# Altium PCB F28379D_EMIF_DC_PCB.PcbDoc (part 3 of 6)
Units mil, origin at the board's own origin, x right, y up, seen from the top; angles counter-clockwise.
Board outline 3000 x 1480 mil, 6 copper layers (Top Layer, Signal Layer 1, Signal Layer 2, Signal Layer 3, Signal Layer 4, Bottom Layer), stack 61.4 mil thick; 51 components, 68 nets, 414 pads, 205 vias.
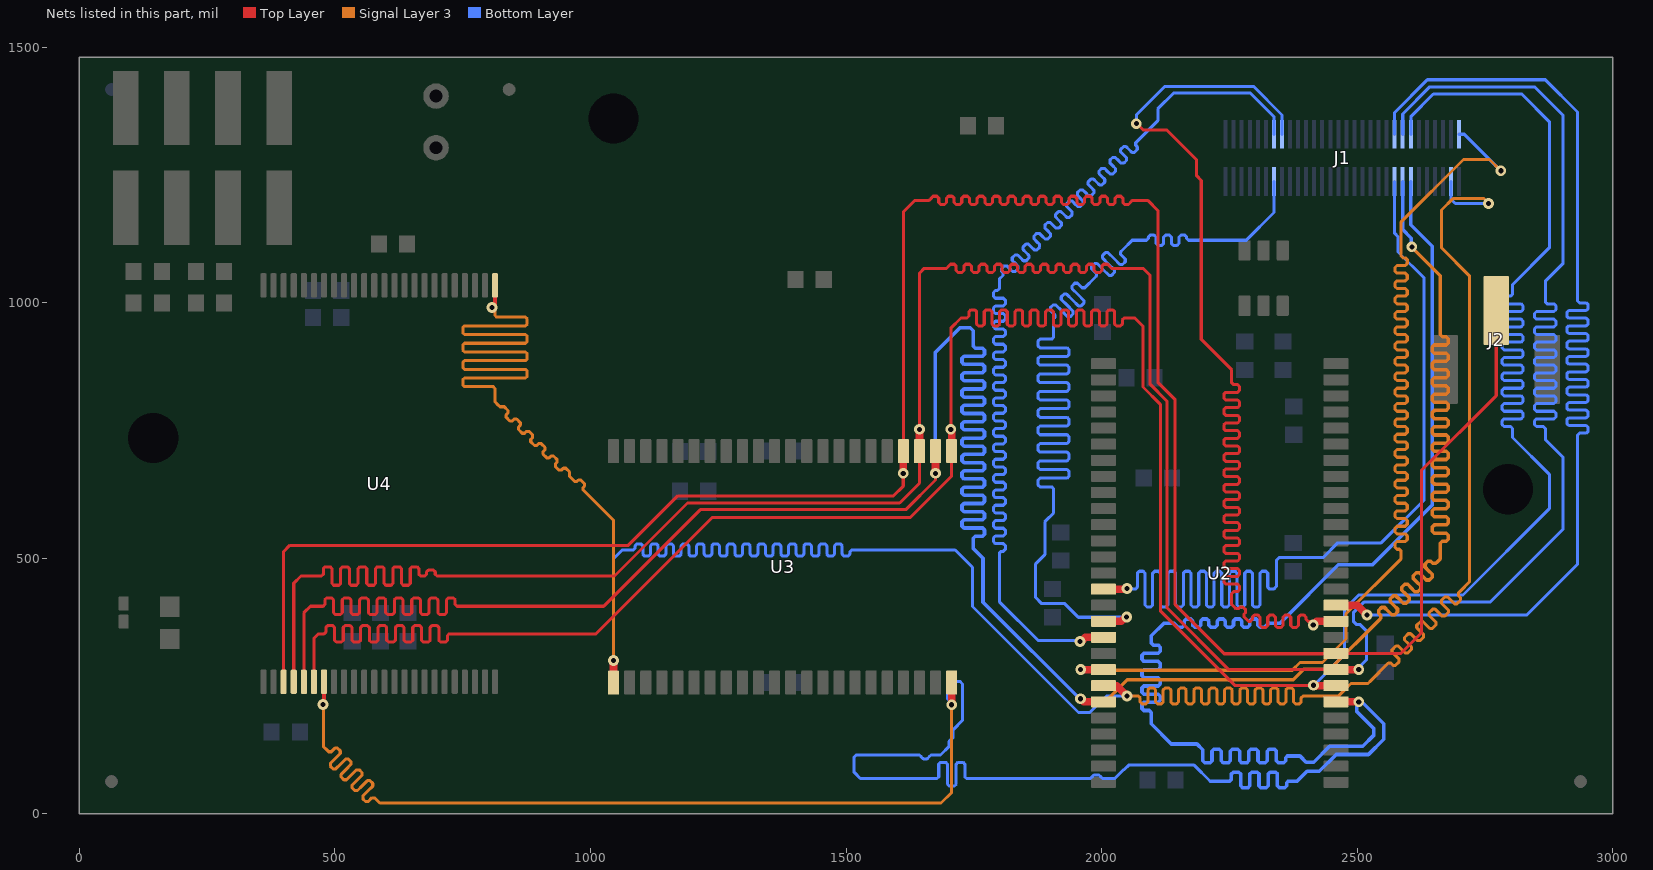
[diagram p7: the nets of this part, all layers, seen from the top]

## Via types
v1: diameter 21, hole 10, Top Layer to Bottom Layer, 204 vias
v2: diameter 20, hole 10, Top Layer to Bottom Layer, 1 vias

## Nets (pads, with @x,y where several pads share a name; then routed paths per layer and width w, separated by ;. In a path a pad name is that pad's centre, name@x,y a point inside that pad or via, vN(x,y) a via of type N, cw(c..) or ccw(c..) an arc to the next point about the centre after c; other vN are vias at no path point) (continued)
EM_A8: J1.13@2604.86,1236.74 U2.33 U3.22 U4.7 | length 6445.8
  Top Layer w8: U4.7@478.73,258.2 478.73,218.27 v1@479,218
  Top Layer w15: v1@1706.71,221.29 U3.22@1706.71,256.62 ; U2.33@2458.36,219.03 v1@2499.03,219.03
  Signal Layer 3 w6: v1@478,218 478,131 485,124 487.65,121.35 492.95,121.35 500.01,128.4 505.31,128.4 510.61,123.1 510.61,117.79 500.91,108.09 491.21,98.39 491.21,93.08 496.51,87.78 501.81,87.78 511.52,97.48 521.22,107.19 526.52,107.19 531.83,101.88 531.83,96.58 522.12,86.88 512.42,77.17 512.42,71.87 517.72,66.57 523.03,66.57 532.73,76.27 542.43,85.97 547.74,85.97 553.04,80.67 553.04,75.37 543.34,65.66 533.63,55.96 533.63,50.66 538.94,45.35 544.24,45.35 553.94,55.06 563.65,64.76 568.95,64.76 574.25,59.46 574.25,54.15 564.55,44.45 554.85,34.75 554.85,29.44 560.15,24.14 565.45,24.14 572.5,31.19 577.81,31.19 588,21 1686,21 1706.71,41.71 v1(1706.71,213.29) v1@1706.71,217.29
  Bottom Layer w6: v1@1706.71,217.29 1699,225 1699,245.62 1712.38,259 1723,259 1728,254 1728,182.75 1709.56,164.31 1709.56,149.25 1705.81,145.5 1705.75,145.5 1702,141.75 1702,132 1685,115 1677.5,115 1666.25,115 1662.5,111.25 1662.5,111.19 1658.75,107.44 1651.25,107.44 1647.5,111.19 1647.5,111.25 1643.75,115 1636,115 1520,115 1516,111 1516,81 1528,69 1673,69 1678.1,69 1681.5,72.4 1681.5,97.12 1684.9,100.52 1695.1,100.52 1698.5,97.12 1698.5,69 1698.5,57.88 1701.9,54.48 1712.1,54.48 1715.5,57.88 1715.5,69 1715.5,97.12 1718.9,100.52 1729.1,100.52 1732.5,97.12 1732.5,72.4 1735.9,69 1817,69 1973,69 1978.1,69 1981.5,72.4 1984.9,75.8 1995.1,75.8 1998.5,72.4 2001.9,69 2016,69 2026,69 2043.5,86.5 2044.5,86.5 2053,95 2181,95 2212,64 2213,64
  Bottom Layer w7: v1@1706.71,221.29 v1@1708.71,219.29 ; 2213,64 2250.4,64 2254,67.6 2254,77.89 2257.6,81.49 2268.4,81.49 2272,77.89 2272,64 2272,54.61 2275.6,51.01 2286.4,51.01 2290,54.61 2290,64 2290,77.89 2293.6,81.49 2304.4,81.49 2308,77.89 2308,64 2308,54.61 2311.6,51.01 2322.4,51.01 2326,54.61 2326,64 2326,77.89 2329.6,81.49 2340.4,81.49 2344,77.89 2344,64 2344,54.61 2347.6,51.01 2358.4,51.01 2362,54.61 2362,60.4 2365.6,64 2371,64 2383,64 2402,83 2426,83 2459,116 2522,116 2552,146 2552,176 2508.97,219.03 v1(2503.03,219.03) 2499.03,219.03 2499.03,199.97 2532,167 2532,153 2511,132 2446,132 2415,101 2400,101 2388,113 2369,113 2363.6,113 2360,109.4 2360,103.62 2356.4,100.02 2345.6,100.02 2342,103.62 2342,113 2342,122.38 2338.4,125.98 2327.6,125.98 2324,122.38 2324,113 2324,103.62 2320.4,100.02 2309.6,100.02 2306,103.62 2306,113 2306,122.38 2302.4,125.98 2291.6,125.98 2288,122.38 2288,113 2288,103.62 2284.4,100.02 2273.6,100.02 2270,103.62 2270,113 2270,122.38 2266.4,125.98 2255.6,125.98 2252,122.38 2252,113 2252,103.62 2248.4,100.02 2237.6,100.02 2234,103.62 2234,113 2234,122.38 2230.4,125.98 2219.6,125.98 2216,122.38 2216,113 2216,103.62 2212.4,100.02 2201.6,100.02 2198,103.62 2198,109.4 2198,125 2186.5,136.5 2136.5,136.5 2097,176 2097,188 2097,198 2093,202 2083,202 2079,206 2079,214 2083,218 2097,218 2111,218 2115,222 2115,230 2111,234 2097,234 2083,234 2079,238 2079,246 2083,250 2097,250 2111,250 2115,254 2115,262 2111,266 2097,266 2083,266 2079,270 2079,278 2083,282 2097,282 2111,282 2115,286 2115,294 2111,298 2097,298 2083,298 2079,302 2079,310 2083,314 2097,314 2111,314 2115,318 2115,326 2111,330 2101,330 2097,334 2097,338 2097,348 2122,373 2130,373 2142,373 2146,369 2150,365 2158,365 2162,369 2162,373 2162,377 2166,381 2174,381 2178,377 2178,373 2178,369 2182,365 2190,365 2194,369 2194,373 2194,377 2198,381 2206,381 2210,377 2210,373 2210,369 2214,365 2222,365 2226,369 2226,373 2226,377 2230,381 2238,381 2242,377 2242,373 2242,369 2246,365 2254,365 2258,369 2258,373 2258,377 2262,381 2270,381 2274,377 2274,373 2274,369 2278,365 2286,365 2290,369 2290,373 2290,377 2294,381 2302,381 2306,377 2306,373 2306,369 2310,365 2318,365 2322,369 2326,373 2338,373 2346,373 2349,373 2463,487 2530,487 2647,604 2647,1110 2604.86,1152.14 J1.13@2604.86,1236.74
  other v1: 477,214
EM_A9: J1.14@2604.86,1329.26 U2.34 U3.23 U4.6 | length 6494.5
  Top Layer w6: U4.6@459.05,258.2 459.05,343.05 468,352 474,352 479.1,352 482.5,355.4 482.5,364.6 485.9,368 496.1,368 499.5,364.6 499.5,352 499.5,339.4 502.9,336 513.1,336 516.5,339.4 516.5,352 516.5,364.6 519.9,368 530.1,368 533.5,364.6 533.5,352 533.5,339.4 536.9,336 547.1,336 550.5,339.4 550.5,352 550.5,364.6 553.9,368 564.1,368 567.5,364.6 567.5,352 567.5,339.4 570.9,336 581.1,336 584.5,339.4 584.5,352 584.5,364.6 587.9,368 598.1,368 601.5,364.6 601.5,352 601.5,339.4 604.9,336 615.1,336 618.5,339.4 618.5,352 618.5,364.6 621.9,368 632.1,368 635.5,364.6 635.5,352 635.5,339.4 638.9,336 649.1,336 652.5,339.4 652.5,352 652.5,364.6 655.9,368 666.1,368 669.5,364.6 669.5,352 669.5,339.4 672.9,336 683.1,336 686.5,339.4 686.5,352 686.5,364.6 689.9,368 700.1,368 703.5,364.6 703.5,352 703.5,339.4 706.9,336 717.1,336 720.5,339.4 720.5,348.6 723.9,352 882,352 1011,352 1239,580 1626,580 1706.71,660.71 U3.23@1706.71,709.38 ; v1(1705,752) 1705,950 1725,970 1733,970 1736.75,970 1740.5,973.75 1740.5,982.18 1744.25,985.93 1751.75,985.93 1755.5,982.18 1755.5,970 1755.5,957.82 1759.25,954.07 1766.75,954.07 1770.5,957.82 1770.5,970 1770.5,982.18 1774.25,985.93 1781.75,985.93 1785.5,982.18 1785.5,970 1785.5,957.82 1789.25,954.07 1796.75,954.07 1800.5,957.82 1800.5,970 1800.5,982.18 1804.25,985.93 1811.75,985.93 1815.5,982.18 1815.5,970 1815.5,957.82 1819.25,954.07 1826.75,954.07 1830.5,957.82 1830.5,970 1830.5,982.18 1834.25,985.93 1841.75,985.93 1845.5,982.18 1845.5,970 1845.5,957.82 1849.25,954.07 1856.75,954.07 1860.5,957.82 1860.5,970 1860.5,982.18 1864.25,985.93 1871.75,985.93 1875.5,982.18 1875.5,970 1875.5,957.82 1879.25,954.07 1886.75,954.07 1890.5,957.82 1890.5,970 1890.5,982.18 1894.25,985.93 1901.75,985.93 1905.5,982.18 1905.5,970 1905.5,957.82 1909.25,954.07 1916.75,954.07 1920.5,957.82 1920.5,970 1920.5,982.18 1924.25,985.93 1931.75,985.93 1935.5,982.18 1935.5,970 1935.5,957.82 1939.25,954.07 1946.75,954.07 1950.5,957.82 1950.5,970 1950.5,982.18 1954.25,985.93 1961.75,985.93 1965.5,982.18 1965.5,970 1965.5,957.82 1969.25,954.07 1976.75,954.07 1980.5,957.82 1980.5,970 1980.5,982.18 1984.25,985.93 1991.75,985.93 1995.5,982.18 1995.5,970 1995.5,957.82 1999.25,954.07 2006.75,954.07 2010.5,957.82 2010.5,970 2010.5,982.18 2014.25,985.93 2021.75,985.93 2025.5,982.18 2025.5,970 2025.5,957.82 2029.25,954.07 2036.75,954.07 2040.5,957.82 2040.5,966.25 2044.25,970 2060,970 2065,970 2081,954 2081,835 2115,801 2115,397 2261.47,250.53 v1@2414.47,250.53 ; v1@1707,749 v1@1708,750
  Top Layer w15: v1(1705,752) 1706.71,750.29 U3.23@1706.71,709.38 ; v1@2414.47,250.53 U2.34@2458.36,250.53
  Bottom Layer w6: v1@2411.47,250.53 2411.53,250.53 v1@2413,252 ; v1@2414.47,250.53 2475,311.06 2475,400 2503,428 2707,428 2876,597 2876,664 2804,736 2804,737 2804,753.75 2800.25,757.5 2787.26,757.5 2783.51,761.25 2783.51,768.75 2787.26,772.5 2804,772.5 2820.74,772.5 2824.49,776.25 2824.49,783.75 2820.74,787.5 2804,787.5 2787.26,787.5 2783.51,791.25 2783.51,798.75 2787.26,802.5 2804,802.5 2820.74,802.5 2824.49,806.25 2824.49,813.75 2820.74,817.5 2804,817.5 2787.26,817.5 2783.51,821.25 2783.51,828.75 2787.26,832.5 2804,832.5 2820.74,832.5 2824.49,836.25 2824.49,843.75 2820.74,847.5 2804,847.5 2787.26,847.5 2783.51,851.25 2783.51,858.75 2787.26,862.5 2804,862.5 2820.74,862.5 2824.49,866.25 2824.49,873.75 2820.74,877.5 2804,877.5 2787.26,877.5 2783.51,881.25 2783.51,888.75 2787.26,892.5 2804,892.5 2820.74,892.5 2824.49,896.25 2824.49,903.75 2820.74,907.5 2804,907.5 2787.26,907.5 2783.51,911.25 2783.51,918.75 2787.26,922.5 2804,922.5 2820.74,922.5 2824.49,926.25 2824.49,933.75 2820.74,937.5 2804,937.5 2787.26,937.5 2783.51,941.25 2783.51,948.75 2787.26,952.5 2804,952.5 2820.74,952.5 2824.49,956.25 2824.49,963.75 2820.74,967.5 2804,967.5 2787.26,967.5 2783.51,971.25 2783.51,978.75 2787.26,982.5 2804,982.5 2820.74,982.5 2824.49,986.25 2824.49,993.75 2820.74,997.5 2804,997.5 2787.26,997.5 2783.51,1001.25 2783.51,1008.75 2787.26,1012.5 2800.25,1012.5 2804,1016.25 2804,1027.5 2804,1035 2876,1107 2876,1354 2822,1408 2649,1408 2604.86,1363.86 J1.14@2604.86,1329.26
  other v1: 2414.47,251.53
EM_A10: J1.15@2589.11,1236.74 U2.22 U3.24 U4.5 | length 6474.8
  Top Layer w6: U4.5@439.36,258.2 439.36,393 452.36,406 472,406 477.1,406 480.5,409.4 480.5,418.6 483.9,422 494.1,422 497.5,418.6 497.5,406 497.5,393.4 500.9,390 511.1,390 514.5,393.4 514.5,406 514.5,418.6 517.9,422 528.1,422 531.5,418.6 531.5,406 531.5,393.4 534.9,390 545.1,390 548.5,393.4 548.5,406 548.5,418.6 551.9,422 562.1,422 565.5,418.6 565.5,406 565.5,393.4 568.9,390 579.1,390 582.5,393.4 582.5,406 582.5,418.6 585.9,422 596.1,422 599.5,418.6 599.5,406 599.5,393.4 602.9,390 613.1,390 616.5,393.4 616.5,406 616.5,418.6 619.9,422 630.1,422 633.5,418.6 633.5,406 633.5,393.4 636.9,390 647.1,390 650.5,393.4 650.5,406 650.5,418.6 653.9,422 664.1,422 667.5,418.6 667.5,406 667.5,393.4 670.9,390 681.1,390 684.5,393.4 684.5,406 684.5,418.6 687.9,422 698.1,422 701.5,418.6 701.5,406 701.5,393.4 704.9,390 715.1,390 718.5,393.4 718.5,406 718.5,418.6 721.9,422 732.1,422 735.5,418.6 735.5,409.4 738.9,406 768,406 1026,406 1215,595 1617,595 1675,653 v1(1675,666)
  Top Layer w15: v1(1675,666) 1675.21,666.21 U3.24@1675.21,709.38 ; v1@1961.46,222.54 1964.97,219.03 U2.22@2003.64,219.03
  Signal Layer 3 w7: v1@1962.97,219.03 2007.03,219.03 2050,262 2375,262 2395.5,282.5 2446.5,282.5 2543.5,379.5 2546.33,382.33 2546.33,387.99 2542.09,392.23 2542.09,397.88 2547.74,403.54 2553.4,403.54 2560.47,396.47 2567.54,389.4 2573.2,389.4 2578.86,395.06 2578.86,400.71 2571.78,407.78 2564.71,414.86 2564.71,420.51 2570.37,426.17 2576.03,426.17 2583.1,419.1 2590.17,412.03 2595.83,412.03 2601.48,417.68 2601.48,423.34 2594.41,430.41 2587.34,437.48 2587.34,443.14 2593,448.8 2598.65,448.8 2605.73,441.73 2612.8,434.65 2618.45,434.65 2624.11,440.31 2624.11,445.97 2617.04,453.04 2609.97,460.11 2609.97,465.77 2615.62,471.42 2621.28,471.42 2628.35,464.35 2635.42,457.28 2641.08,457.28 2646.74,462.94 2646.74,468.6 2639.67,475.67 2632.6,482.74 2632.6,488.39 2638.25,494.05 2643.91,494.05 2648.15,489.81 2653.81,489.81 2656.5,492.5 2662.5,498.5 2662.5,515 2662.5,529 2666.5,533 2673.89,533 2677.89,537 2677.89,545 2673.89,549 2662.5,549 2651.11,549 2647.11,553 2647.11,561 2651.11,565 2662.5,565 2673.89,565 2677.89,569 2677.89,577 2673.89,581 2662.5,581 2651.11,581 2647.11,585 2647.11,593 2651.11,597 2662.5,597 2673.89,597 2677.89,601 2677.89,609 2673.89,613 2662.5,613 2651.11,613 2647.11,617 2647.11,625 2651.11,629 2662.5,629 2673.89,629 2677.89,633 2677.89,641 2673.89,645 2662.5,645 2651.11,645 2647.11,649 2647.11,657 2651.11,661 2662.5,661 2673.89,661 2677.89,665 2677.89,673 2673.89,677 2662.5,677 2651.11,677 2647.11,681 2647.11,689 2651.11,693 2662.5,693 2673.89,693 2677.89,697 2677.89,705 2673.89,709 2662.5,709 2651.11,709 2647.11,713 2647.11,721 2651.11,725 2662.5,725 2673.89,725 2677.89,729 2677.89,737 2673.89,741 2662.5,741 2651.11,741 2647.11,745 2647.11,753 2651.11,757 2662.5,757 2673.89,757 2677.89,761 2677.89,769 2673.89,773 2662.5,773 2651.11,773 2647.11,777 2647.11,785 2651.11,789 2662.5,789 2673.89,789 2677.89,793 2677.89,801 2673.89,805 2662.5,805 2651.11,805 2647.11,809 2647.11,817 2651.11,821 2662.5,821 2673.89,821 2677.89,825 2677.89,833 2673.89,837 2662.5,837 2651.11,837 2647.11,841 2647.11,849 2651.11,853 2662.5,853 2673.89,853 2677.89,857 2677.89,865 2673.89,869 2662.5,869 2651.11,869 2647.11,873 2647.11,881 2651.11,885 2662.5,885 2673.89,885 2677.89,889 2677.89,897 2673.89,901 2662.5,901 2651.11,901 2647.11,905 2647.11,913 2651.11,917 2662.5,917 2673.89,917 2677.89,921 2677.89,929 2673.89,933 2666.5,933 2662.5,937 2662.5,941 2662.5,1052.5 v1@2606,1109
  Bottom Layer w7: v1@1675,670 1675,903 1723,951 1743,951 1749,945 1749,915 1753,911 1767,911 1771,907 1771,899 1767,895 1749,895 1731,895 1727,891 1727,883 1731,879 1749,879 1767,879 1771,875 1771,867 1767,863 1749,863 1731,863 1727,859 1727,851 1731,847 1749,847 1767,847 1771,843 1771,835 1767,831 1749,831 1731,831 1727,827 1727,819 1731,815 1749,815 1767,815 1771,811 1771,803 1767,799 1749,799 1731,799 1727,795 1727,787 1731,783 1749,783 1767,783 1771,779 1771,771 1767,767 1749,767 1731,767 1727,763 1727,755 1731,751 1749,751 1767,751 1771,747 1771,739 1767,735 1749,735 1731,735 1727,731 1727,723 1731,719 1749,719 1767,719 1771,715 1771,707 1767,703 1749,703 1731,703 1727,699 1727,691 1731,687 1749,687 1767,687 1771,683 1771,675 1767,671 1749,671 1731,671 1727,667 1727,659 1731,655 1749,655 1767,655 1771,651 1771,643 1767,639 1749,639 1731,639 1727,635 1727,627 1731,623 1749,623 1767,623 1771,619 1771,611 1767,607 1749,607 1731,607 1727,603 1727,595 1731,591 1749,591 1767,591 1771,587 1771,579 1767,575 1749,575 1731,575 1727,571 1727,563 1731,559 1749,559 1767,559 1771,555 1771,547 1767,543 1753,543 1749,539 1749,527 1749,519 1768,500 1768,414 v1@1962.97,219.03 ; J1.15@2589.11,1236.74 2589.11,1142.89 2606,1126 v1@2606,1109
  other v1: 1958.97,225.03 2607,1109
EM_A11: J1.16@2589.11,1329.26 U2.35 U3.25 U4.4 | length 6498.6
  Top Layer w6: U4.4@419.68,258.2 419.68,451 433.68,465 469,465 474.1,465 477.5,468.4 477.5,479.6 480.9,483 491.1,483 494.5,479.6 494.5,465 494.5,450.4 497.9,447 508.1,447 511.5,450.4 511.5,465 511.5,479.6 514.9,483 525.1,483 528.5,479.6 528.5,465 528.5,450.4 531.9,447 542.1,447 545.5,450.4 545.5,465 545.5,479.6 548.9,483 559.1,483 562.5,479.6 562.5,465 562.5,450.4 565.9,447 576.1,447 579.5,450.4 579.5,465 579.5,479.6 582.9,483 593.1,483 596.5,479.6 596.5,465 596.5,450.4 599.9,447 610.1,447 613.5,450.4 613.5,465 613.5,479.6 616.9,483 627.1,483 630.5,479.6 630.5,465 630.5,450.4 633.9,447 644.1,447 647.5,450.4 647.5,465 647.5,479.6 650.9,483 661.1,483 664.5,479.6 664.5,468.4 667.9,465 671,465 676.1,465 679.5,468.4 679.5,473.16 682.9,476.56 693.1,476.56 696.5,473.16 696.5,468.4 699.9,465 752,465 1047,465 1190,608 1605,608 1643.72,646.72 U3.25@1643.72,709.38 ; v1@1644,749 v1(1644,752) 1644,1058 1653,1067 1693,1067 1696.75,1067 1700.5,1070.75 1700.5,1071.25 1704.25,1075 1711.75,1075 1715.5,1071.25 1715.5,1067 1715.5,1062.75 1719.25,1059 1726.75,1059 1730.5,1062.75 1730.5,1067 1730.5,1071.25 1734.25,1075 1741.75,1075 1745.5,1071.25 1745.5,1067 1745.5,1062.75 1749.25,1059 1756.75,1059 1760.5,1062.75 1760.5,1067 1760.5,1071.25 1764.25,1075 1771.75,1075 1775.5,1071.25 1775.5,1067 1775.5,1062.75 1779.25,1059 1786.75,1059 1790.5,1062.75 1790.5,1067 1790.5,1071.25 1794.25,1075 1801.75,1075 1805.5,1071.25 1805.5,1067 1805.5,1062.75 1809.25,1059 1816.75,1059 1820.5,1062.75 1820.5,1067 1820.5,1071.25 1824.25,1075 1831.75,1075 1835.5,1071.25 1835.5,1067 1835.5,1062.75 1839.25,1059 1846.75,1059 1850.5,1062.75 1850.5,1067 1850.5,1071.25 1854.25,1075 1861.75,1075 1865.5,1071.25 1865.5,1067 1865.5,1062.75 1869.25,1059 1876.75,1059 1880.5,1062.75 1880.5,1067 1880.5,1071.25 1884.25,1075 1891.75,1075 1895.5,1071.25 1895.5,1067 1895.5,1062.75 1899.25,1059 1906.75,1059 1910.5,1062.75 1910.5,1067 1910.5,1071.25 1914.25,1075 1921.75,1075 1925.5,1071.25 1925.5,1067 1925.5,1062.75 1929.25,1059 1936.75,1059 1940.5,1062.75 1940.5,1067 1940.5,1071.25 1944.25,1075 1951.75,1075 1955.5,1071.25 1955.5,1067 1955.5,1062.75 1959.25,1059 1966.75,1059 1970.5,1062.75 1970.5,1067 1970.5,1071.25 1974.25,1075 1981.75,1075 1985.5,1071.25 1985.5,1067 1985.5,1062.75 1989.25,1059 1996.75,1059 2000.5,1062.75 2000.5,1067 2000.5,1071.25 2004.25,1075 2011.75,1075 2015.5,1071.25 2015.5,1070.75 2019.25,1067 2075,1067 2081,1067 2095,1053 2095,840 2128,807 2128,403 2248.98,282.02 U2.35@2458.36,282.02
  Top Layer w15: U3.25@1643.72,709.38 1643.72,744.72 v1@1644,745 ; U2.35@2458.36,282.02 v1@2499.98,282.02
  Bottom Layer w6: v1@2499.98,282.02 2499.98,282.98 2518,301 2518,358 2506,370 2499,370 2492.5,376.5 2492.5,393.5 2513,414 2760,414 2903,557 2903,697 2868,732 2868,753.75 2864.25,757.5 2850.8,757.5 2847.05,761.25 2847.05,768.75 2850.8,772.5 2868,772.5 2885.2,772.5 2888.95,776.25 2888.95,783.75 2885.2,787.5 2868,787.5 2850.8,787.5 2847.05,791.25 2847.05,798.75 2850.8,802.5 2868,802.5 2885.2,802.5 2888.95,806.25 2888.95,813.75 2885.2,817.5 2868,817.5 2850.8,817.5 2847.05,821.25 2847.05,828.75 2850.8,832.5 2868,832.5 2885.2,832.5 2888.95,836.25 2888.95,843.75 2885.2,847.5 2868,847.5 2850.8,847.5 2847.05,851.25 2847.05,858.75 2850.8,862.5 2868,862.5 2885.2,862.5 2888.95,866.25 2888.95,873.75 2885.2,877.5 2868,877.5 2850.8,877.5 2847.05,881.25 2847.05,888.75 2850.8,892.5 2868,892.5 2885.2,892.5 2888.95,896.25 2888.95,903.75 2885.2,907.5 2868,907.5 2850.8,907.5 2847.05,911.25 2847.05,918.75 2850.8,922.5 2868,922.5 2885.2,922.5 2888.95,926.25 2888.95,933.75 2885.2,937.5 2868,937.5 2850.8,937.5 2847.05,941.25 2847.05,948.75 2850.8,952.5 2868,952.5 2885.2,952.5 2888.95,956.25 2888.95,963.75 2885.2,967.5 2868,967.5 2850.8,967.5 2847.05,971.25 2847.05,978.75 2850.8,982.5 2868,982.5 2885.2,982.5 2888.95,986.25 2888.95,993.75 2885.2,997.5 2871.75,997.5 2868,1001.25 2868,1005 2868,1042 2903,1077 2903,1366 2847,1422 2642,1422 2589.11,1369.11 J1.16@2589.11,1329.26
  other v1: 2502.98,282.02
EM_A12: J2.2 U2.36 U3.26 U4.3 | length 4883.8
  Top Layer w6: U4.3@399.99,258.2 399.99,513 411.99,525 1074,525 1171,622 1593,622 1612,641 v1@1612,670 ; U3.26@1612.22,709.38 1612.22,1177.22 1635,1200 1659,1200 1662.75,1200 1666.5,1203.75 1666.5,1204.25 1670.25,1208 1677.75,1208 1681.5,1204.25 1681.5,1200 1681.5,1195.75 1685.25,1192 1692.75,1192 1696.5,1195.75 1696.5,1200 1696.5,1204.25 1700.25,1208 1707.75,1208 1711.5,1204.25 1711.5,1200 1711.5,1195.75 1715.25,1192 1722.75,1192 1726.5,1195.75 1726.5,1200 1726.5,1204.25 1730.25,1208 1737.75,1208 1741.5,1204.25 1741.5,1200 1741.5,1195.75 1745.25,1192 1752.75,1192 1756.5,1195.75 1756.5,1200 1756.5,1204.25 1760.25,1208 1767.75,1208 1771.5,1204.25 1771.5,1200 1771.5,1195.75 1775.25,1192 1782.75,1192 1786.5,1195.75 1786.5,1200 1786.5,1204.25 1790.25,1208 1797.75,1208 1801.5,1204.25 1801.5,1200 1801.5,1195.75 1805.25,1192 1812.75,1192 1816.5,1195.75 1816.5,1200 1816.5,1204.25 1820.25,1208 1827.75,1208 1831.5,1204.25 1831.5,1200 1831.5,1195.75 1835.25,1192 1842.75,1192 1846.5,1195.75 1846.5,1200 1846.5,1204.25 1850.25,1208 1857.75,1208 1861.5,1204.25 1861.5,1200 1861.5,1195.75 1865.25,1192 1872.75,1192 1876.5,1195.75 1876.5,1200 1876.5,1204.25 1880.25,1208 1887.75,1208 1891.5,1204.25 1891.5,1200 1891.5,1195.75 1895.25,1192 1902.75,1192 1906.5,1195.75 1906.5,1200 1906.5,1204.25 1910.25,1208 1917.75,1208 1921.5,1204.25 1921.5,1200 1921.5,1195.75 1925.25,1192 1932.75,1192 1936.5,1195.75 1936.5,1200 1936.5,1204.25 1940.25,1208 1947.75,1208 1951.5,1204.25 1951.5,1200 1951.5,1195.75 1955.25,1192 1962.75,1192 1966.5,1195.75 1966.5,1200 1966.5,1204.25 1970.25,1208 1977.75,1208 1981.5,1204.25 1981.5,1200 1981.5,1195.75 1985.25,1192 1992.75,1192 1996.5,1195.75 1996.5,1200 1996.5,1204.25 2000.25,1208 2007.75,1208 2011.5,1204.25 2011.5,1200 2011.5,1195.75 2015.25,1192 2022.75,1192 2026.5,1195.75 2026.5,1200 2026.5,1204.25 2030.25,1208 2037.75,1208 2041.5,1204.25 2041.5,1200 2041.5,1195.75 2045.25,1192 2052.75,1192 2056.5,1195.75 2056.5,1196.25 2060.25,1200 2068,1200 2090,1200 2110,1180 2110,844 2144,810 2144,409 2240,313 2457.84,313 U2.36@2458.36,313.52 2585.52,313.52 2626,354 2626,672 2772,818 J2.2@2772,984.48
  Top Layer w15: v1@1612,670 1612.22,670.22 U3.26@1612.22,709.38
  other v1: 1612,666
EM_A13_CAS: J1.47@2337.14,1236.74 U2.17 | length 2708.9
  Top Layer w15: U2.17@2003.64,376.51 2038.51,376.51 v1@2046.51,384.51
  Bottom Layer w6: v1@2046.51,384.51 1954.49,384.51 1928,411 1883,411 1871,423 1871,489 1889,507 1889,571 1892,574 1906,588 1906,610 1906,622.5 1906,636.1 1902.6,639.5 1879.4,639.5 1876,642.9 1876,653.1 1879.4,656.5 1906,656.5 1932.6,656.5 1936,659.9 1936,670.1 1932.6,673.5 1906,673.5 1879.4,673.5 1876,676.9 1876,687.1 1879.4,690.5 1906,690.5 1932.6,690.5 1936,693.9 1936,704.1 1932.6,707.5 1906,707.5 1879.4,707.5 1876,710.9 1876,721.1 1879.4,724.5 1906,724.5 1932.6,724.5 1936,727.9 1936,738.1 1932.6,741.5 1906,741.5 1879.4,741.5 1876,744.9 1876,755.1 1879.4,758.5 1906,758.5 1932.6,758.5 1936,761.9 1936,772.1 1932.6,775.5 1906,775.5 1879.4,775.5 1876,778.9 1876,789.1 1879.4,792.5 1906,792.5 1932.6,792.5 1936,795.9 1936,806.1 1932.6,809.5 1906,809.5 1879.4,809.5 1876,812.9 1876,823.1 1879.4,826.5 1906,826.5 1932.6,826.5 1936,829.9 1936,840.1 1932.6,843.5 1906,843.5 1879.4,843.5 1876,846.9 1876,857.1 1879.4,860.5 1906,860.5 1932.6,860.5 1936,863.9 1936,874.1 1932.6,877.5 1906,877.5 1879.4,877.5 1876,880.9 1876,891.1 1879.4,894.5 1906,894.5 1932.6,894.5 1936,897.9 1936,908.1 1932.6,911.5 1906,911.5 1879.4,911.5 1876,914.9 1876,925.1 1879.4,928.5 1902.6,928.5 1906,931.9 1906,945.5 1906,954 1906,968 1908.65,970.65 1908.65,975.95 1899.81,984.79 1899.81,990.1 1905.12,995.4 1910.42,995.4 1921.91,983.91 1933.4,972.42 1938.7,972.42 1944.01,977.72 1944.01,983.03 1932.52,994.52 1921.03,1006.01 1921.03,1011.31 1926.33,1016.61 1931.63,1016.61 1943.12,1005.12 1954.61,993.63 1959.92,993.63 1965.22,998.94 1965.22,1004.24 1953.73,1015.73 1942.24,1027.22 1942.24,1032.52 1947.54,1037.83 1952.85,1037.83 1961.68,1028.99 1966.99,1028.99 1987,1049 1989.65,1051.65 1989.65,1056.95 1980.81,1065.79 1980.81,1071.1 1986.12,1076.4 1991.42,1076.4 2002.91,1064.91 2014.4,1053.42 2019.7,1053.42 2025.01,1058.72 2025.01,1064.03 2013.52,1075.52 2002.03,1087.01 2002.03,1092.31 2007.33,1097.61 2012.63,1097.61 2024.12,1086.12 2035.61,1074.63 2040.92,1074.63 2046.22,1079.94 2046.22,1085.24 2037.38,1094.08 2037.38,1099.38 2041,1103 2060,1122 2084,1122 2087.75,1122 2091.5,1125.75 2091.5,1128.25 2095.25,1132 2102.75,1132 2106.5,1128.25 2106.5,1122 2106.5,1115.75 2110.25,1112 2117.75,1112 2121.5,1115.75 2121.5,1122 2121.5,1128.25 2125.25,1132 2132.75,1132 2136.5,1128.25 2136.5,1122 2136.5,1115.75 2140.25,1112 2147.75,1112 2151.5,1115.75 2151.5,1122 2151.5,1128.25 2155.25,1132 2162.75,1132 2166.5,1128.25 2166.5,1125.5 2170,1122 2283,1122 2337.14,1176.14 J1.47@2337.14,1236.74
  other v1: 2049,385
EM_A14_RAS: J1.48@2337.14,1329.26 U2.18 | length 2709.2
  Top Layer w15: v1@1961.98,339.02 1967.98,345.02 U2.18@2003.64,345.02
  Bottom Layer w6: v1@1961.98,339.02 1875.98,339.02 1800,415 1800,423 1800,509.75 1803.75,513.5 1807.88,513.5 1811.63,517.25 1811.63,524.75 1807.88,528.5 1800,528.5 1792.12,528.5 1788.37,532.25 1788.37,539.75 1792.12,543.5 1800,543.5 1807.88,543.5 1811.63,547.25 1811.63,554.75 1807.88,558.5 1800,558.5 1792.12,558.5 1788.37,562.25 1788.37,569.75 1792.12,573.5 1800,573.5 1807.88,573.5 1811.63,577.25 1811.63,584.75 1807.88,588.5 1800,588.5 1792.12,588.5 1788.37,592.25 1788.37,599.75 1792.12,603.5 1800,603.5 1807.88,603.5 1811.63,607.25 1811.63,614.75 1807.88,618.5 1800,618.5 1792.12,618.5 1788.37,622.25 1788.37,629.75 1792.12,633.5 1800,633.5 1807.88,633.5 1811.63,637.25 1811.63,644.75 1807.88,648.5 1800,648.5 1792.12,648.5 1788.37,652.25 1788.37,659.75 1792.12,663.5 1800,663.5 1807.88,663.5 1811.63,667.25 1811.63,674.75 1807.88,678.5 1800,678.5 1792.12,678.5 1788.37,682.25 1788.37,689.75 1792.12,693.5 1800,693.5 1807.88,693.5 1811.63,697.25 1811.63,704.75 1807.88,708.5 1800,708.5 1792.12,708.5 1788.37,712.25 1788.37,719.75 1792.12,723.5 1800,723.5 1807.88,723.5 1811.63,727.25 1811.63,734.75 1807.88,738.5 1800,738.5 1792.12,738.5 1788.37,742.25 1788.37,749.75 1792.12,753.5 1800,753.5 1807.88,753.5 1811.63,757.25 1811.63,764.75 1807.88,768.5 1800,768.5 1792.12,768.5 1788.37,772.25 1788.37,779.75 1792.12,783.5 1800,783.5 1807.88,783.5 1811.63,787.25 1811.63,794.75 1807.88,798.5 1800,798.5 1792.12,798.5 1788.37,802.25 1788.37,809.75 1792.12,813.5 1800,813.5 1807.88,813.5 1811.63,817.25 1811.63,824.75 1807.88,828.5 1800,828.5 1792.12,828.5 1788.37,832.25 1788.37,839.75 1792.12,843.5 1800,843.5 1807.88,843.5 1811.63,847.25 1811.63,854.75 1807.88,858.5 1800,858.5 1792.12,858.5 1788.37,862.25 1788.37,869.75 1792.12,873.5 1800,873.5 1807.88,873.5 1811.63,877.25 1811.63,884.75 1807.88,888.5 1800,888.5 1792.12,888.5 1788.37,892.25 1788.37,899.75 1792.12,903.5 1800,903.5 1807.88,903.5 1811.63,907.25 1811.63,914.75 1807.88,918.5 1800,918.5 1792.12,918.5 1788.37,922.25 1788.37,929.75 1792.12,933.5 1800,933.5 1807.88,933.5 1811.63,937.25 1811.63,944.75 1807.88,948.5 1800,948.5 1792.12,948.5 1788.37,952.25 1788.37,959.75 1792.12,963.5 1800,963.5 1807.88,963.5 1811.63,967.25 1811.63,974.75 1807.88,978.5 1800,978.5 1792.12,978.5 1788.37,982.25 1788.37,989.75 1792.12,993.5 1800,993.5 1807.88,993.5 1811.63,997.25 1811.63,1004.75 1807.88,1008.5 1800,1008.5 1792.12,1008.5 1788.37,1012.25 1788.37,1019.75 1792.12,1023.5 1796.25,1023.5 1800,1027.25 1800,1038.5 1800,1046 1806.99,1052.99 1806.99,1058.29 1804.07,1061.21 1804.07,1066.51 1809.37,1071.82 1814.67,1071.82 1820.24,1066.24 1825.82,1060.67 1831.12,1060.67 1836.42,1065.98 1836.42,1071.28 1830.85,1076.85 1825.28,1082.42 1825.28,1087.73 1830.58,1093.03 1835.89,1093.03 1841.46,1087.46 1847.03,1081.89 1852.33,1081.89 1857.64,1087.19 1857.64,1092.49 1852.06,1098.06 1846.49,1103.64 1846.49,1108.94 1851.8,1114.24 1857.1,1114.24 1862.67,1108.67 1868.24,1103.1 1873.55,1103.1 1878.85,1108.4 1878.85,1113.71 1873.28,1119.28 1867.71,1124.85 1867.71,1130.15 1873.01,1135.46 1878.31,1135.46 1883.88,1129.88 1889.46,1124.31 1894.76,1124.31 1900.06,1129.62 1900.06,1134.92 1894.49,1140.49 1888.92,1146.06 1888.92,1151.37 1894.22,1156.67 1899.53,1156.67 1905.1,1151.1 1910.67,1145.53 1915.97,1145.53 1921.28,1150.83 1921.28,1156.13 1915.7,1161.7 1910.13,1167.28 1910.13,1172.58 1915.44,1177.88 1920.74,1177.88 1926.31,1172.31 1931.88,1166.74 1937.19,1166.74 1942.49,1172.04 1942.49,1177.35 1936.92,1182.92 1931.35,1188.49 1931.35,1193.79 1936.65,1199.1 1941.95,1199.1 1947.52,1193.52 1953.1,1187.95 1958.4,1187.95 1963.7,1193.26 1963.7,1198.56 1958.13,1204.13 1952.56,1209.7 1952.56,1215.01 1957.86,1220.31 1963.17,1220.31 1968.74,1214.74 1974.31,1209.17 1979.61,1209.17 1984.92,1214.47 1984.92,1219.77 1979.34,1225.34 1973.77,1230.92 1973.77,1236.22 1979.08,1241.52 1984.38,1241.52 1989.95,1235.95 1995.52,1230.38 2000.83,1230.38 2006.13,1235.68 2006.13,1240.99 2000.56,1246.56 1994.99,1252.13 1994.99,1257.43 2000.29,1262.74 2005.59,1262.74 2011.16,1257.16 2016.74,1251.59 2022.04,1251.59 2027.34,1256.89 2027.34,1262.2 2021.77,1267.77 2016.2,1273.34 2016.2,1278.65 2021.5,1283.95 2026.8,1283.95 2032.38,1278.38 2037.95,1272.8 2043.25,1272.8 2048.56,1278.11 2048.56,1283.41 2042.98,1288.98 2037.41,1294.56 2037.41,1299.86 2042.71,1305.16 2048.02,1305.16 2053.59,1299.59 2059.16,1294.02 2064.47,1294.02 2069.77,1299.32 2069.77,1304.62 2066.85,1307.55 2066.85,1312.85 2069.5,1315.5 2110,1356 2110,1379 2141,1410 2291,1410 2337.14,1363.86 J1.48@2337.14,1329.26
  other v1: 1957.98,337.02
EM_A15_DQM0: J1.17@2573.36,1236.74 U2.15 | length 2485.9
  Top Layer w15: U2.15@2003.64,439.5 v1@2049.5,439.5
  Bottom Layer w6: v1@2049.5,439.5 2066.25,439.5 2070,443.25 2070,470.72 2073.75,474.47 2081.25,474.47 2085,470.72 2085,439.5 2085,408.29 2088.75,404.54 2096.25,404.54 2100,408.29 2100,439.5 2100,470.72 2103.75,474.47 2111.25,474.47 2115,470.72 2115,439.5 2115,408.29 2118.75,404.54 2126.25,404.54 2130,408.29 2130,439.5 2130,470.72 2133.75,474.47 2141.25,474.47 2145,470.72 2145,439.5 2145,408.29 2148.75,404.54 2156.25,404.54 2160,408.29 2160,439.5 2160,470.72 2163.75,474.47 2171.25,474.47 2175,470.72 2175,439.5 2175,408.29 2178.75,404.54 2186.25,404.54 2190,408.29 2190,439.5 2190,470.72 2193.75,474.47 2201.25,474.47 2205,470.72 2205,439.5 2205,408.29 2208.75,404.54 2216.25,404.54 2220,408.29 2220,439.5 2220,470.72 2223.75,474.47 2231.25,474.47 2235,470.72 2235,439.5 2235,408.29 2238.75,404.54 2246.25,404.54 2250,408.29 2250,439.5 2250,470.72 2253.75,474.47 2261.25,474.47 2265,470.72 2265,439.5 2265,408.29 2268.75,404.54 2276.25,404.54 2280,408.29 2280,439.5 2280,470.72 2283.75,474.47 2291.25,474.47 2295,470.72 2295,439.5 2295,408.29 2298.75,404.54 2306.25,404.54 2310,408.29 2310,439.5 2310,470.72 2313.75,474.47 2321.25,474.47 2325,470.72 2325,443.25 2328.75,439.5 2336.5,439.5 2342,445 2342,496 2347,501 2433,501 2462,530 2547,530 2631,614 2631,1048 2580,1099 2580,1129 2573.36,1135.64 J1.17@2573.36,1236.74
  other v1: 2049.5,440.5
EM_A16_DQM1: J1.18@2573.36,1329.26 U2.39 | length 2485.9
  Top Layer w15: U2.39@2458.36,408.01 2499.99,408.01 v1(2519,389)
  Bottom Layer w6: v1(2519,389) 2832,389 2931,488 2931,585 2931,740.75 2934.75,744.5 2948,744.5 2951.75,748.25 2951.75,755.75 2948,759.5 2931,759.5 2914,759.5 2910.25,763.25 2910.25,770.75 2914,774.5 2931,774.5 2948,774.5 2951.75,778.25 2951.75,785.75 2948,789.5 2931,789.5 2914,789.5 2910.25,793.25 2910.25,800.75 2914,804.5 2931,804.5 2948,804.5 2951.75,808.25 2951.75,815.75 2948,819.5 2931,819.5 2914,819.5 2910.25,823.25 2910.25,830.75 2914,834.5 2931,834.5 2948,834.5 2951.75,838.25 2951.75,845.75 2948,849.5 2931,849.5 2914,849.5 2910.25,853.25 2910.25,860.75 2914,864.5 2931,864.5 2948,864.5 2951.75,868.25 2951.75,875.75 2948,879.5 2931,879.5 2914,879.5 2910.25,883.25 2910.25,890.75 2914,894.5 2931,894.5 2948,894.5 2951.75,898.25 2951.75,905.75 2948,909.5 2931,909.5 2914,909.5 2910.25,913.25 2910.25,920.75 2914,924.5 2931,924.5 2948,924.5 2951.75,928.25 2951.75,935.75 2948,939.5 2931,939.5 2914,939.5 2910.25,943.25 2910.25,950.75 2914,954.5 2931,954.5 2948,954.5 2951.75,958.25 2951.75,965.75 2948,969.5 2931,969.5 2914,969.5 2910.25,973.25 2910.25,980.75 2914,984.5 2931,984.5 2948,984.5 2951.75,988.25 2951.75,995.75 2948,999.5 2934.75,999.5 2931,1003.25 2931,1007 2931,1373 2868,1436 2637.36,1436 2573.36,1372 J1.18@2573.36,1329.26
EM_BA0: J1.2@2699.35,1329.26 U2.20 | length 2550.7
  Top Layer w15: v1@1962.02,282.02 U2.20@2003.64,282.02
  Signal Layer 3 w6: v1@1962.02,282.02 1963.3,280.75 2373,280.75 2388.25,296 2432,296 2478,342 2478,391 2586,499 2586,508 2586,513.75 2582.25,517.5 2577.75,517.5 2574,521.25 2574,528.75 2577.75,532.5 2586,532.5 2594.25,532.5 2598,536.25 2598,543.75 2594.25,547.5 2586,547.5 2577.75,547.5 2574,551.25 2574,558.75 2577.75,562.5 2586,562.5 2594.25,562.5 2598,566.25 2598,573.75 2594.25,577.5 2586,577.5 2577.75,577.5 2574,581.25 2574,588.75 2577.75,592.5 2586,592.5 2594.25,592.5 2598,596.25 2598,603.75 2594.25,607.5 2586,607.5 2577.75,607.5 2574,611.25 2574,618.75 2577.75,622.5 2586,622.5 2594.25,622.5 2598,626.25 2598,633.75 2594.25,637.5 2586,637.5 2577.75,637.5 2574,641.25 2574,648.75 2577.75,652.5 2586,652.5 2594.25,652.5 2598,656.25 2598,663.75 2594.25,667.5 2586,667.5 2577.75,667.5 2574,671.25 2574,678.75 2577.75,682.5 2586,682.5 2594.25,682.5 2598,686.25 2598,693.75 2594.25,697.5 2586,697.5 2577.75,697.5 2574,701.25 2574,708.75 2577.75,712.5 2586,712.5 2594.25,712.5 2598,716.25 2598,723.75 2594.25,727.5 2586,727.5 2577.75,727.5 2574,731.25 2574,738.75 2577.75,742.5 2586,742.5 2594.25,742.5 2598,746.25 2598,753.75 2594.25,757.5 2586,757.5 2577.75,757.5 2574,761.25 2574,768.75 2577.75,772.5 2586,772.5 2594.25,772.5 2598,776.25 2598,783.75 2594.25,787.5 2586,787.5 2577.75,787.5 2574,791.25 2574,798.75 2577.75,802.5 2586,802.5 2594.25,802.5 2598,806.25 2598,813.75 2594.25,817.5 2586,817.5 2577.75,817.5 2574,821.25 2574,828.75 2577.75,832.5 2586,832.5 2594.25,832.5 2598,836.25 2598,843.75 2594.25,847.5 2586,847.5 2577.75,847.5 2574,851.25 2574,858.75 2577.75,862.5 2586,862.5 2594.25,862.5 2598,866.25 2598,873.75 2594.25,877.5 2586,877.5 2577.75,877.5 2574,881.25 2574,888.75 2577.75,892.5 2586,892.5 2594.25,892.5 2598,896.25 2598,903.75 2594.25,907.5 2586,907.5 2577.75,907.5 2574,911.25 2574,918.75 2577.75,922.5 2586,922.5 2594.25,922.5 2598,926.25 2598,933.75 2594.25,937.5 2586,937.5 2577.75,937.5 2574,941.25 2574,948.75 2577.75,952.5 2586,952.5 2594.25,952.5 2598,956.25 2598,963.75 2594.25,967.5 2586,967.5 2577.75,967.5 2574,971.25 2574,978.75 2577.75,982.5 2586,982.5 2594.25,982.5 2598,986.25 2598,993.75 2594.25,997.5 2586,997.5 2577.75,997.5 2574,1001.25 2574,1008.75 2577.75,1012.5 2586,1012.5 2594.25,1012.5 2598,1016.25 2598,1023.75 2594.25,1027.5 2586,1027.5 2577.75,1027.5 2574,1031.25 2574,1038.75 2577.75,1042.5 2586,1042.5 2594.25,1042.5 2598,1046.25 2598,1053.75 2594.25,1057.5 2586,1057.5 2577.75,1057.5 2574,1061.25 2574,1068.75 2577.75,1072.5 2586,1072.5 2594.25,1072.5 2598,1076.25 2598,1083.75 2594.25,1087.5 2589.75,1087.5 2586,1091.25 2586,1095 2586,1158 2708,1280 2759,1280 v1(2781,1258)
  Bottom Layer w6: J1.2@2699.35,1329.26 2709.74,1329.26 v1(2781,1258)
  other v1: 1959.02,282.02
EM_BA1: J1.3@2683.6,1236.74 U2.21 U3.1 U4.25 | length 6474.8
  Top Layer w8: v1(807.38,990.38) 813.38,996.38 U4.25@813.38,1033.8
  Top Layer w15: v1@1045,291 1045.29,290.71 U3.1@1045.29,256.62 ; U2.21@2003.64,250.53 2029.53,250.53 v1(2049.53,230.53)
  Signal Layer 3 w6: v1(807.38,990.38) 813.38,984.38 813.38,974.9 816.78,971.5 872.98,971.5 876.38,968.1 876.38,957.9 872.98,954.5 813.38,954.5 753.78,954.5 750.38,951.1 750.38,940.9 753.78,937.5 813.38,937.5 872.98,937.5 876.38,934.1 876.38,923.9 872.98,920.5 813.38,920.5 753.78,920.5 750.38,917.1 750.38,906.9 753.78,903.5 813.38,903.5 872.98,903.5 876.38,900.1 876.38,889.9 872.98,886.5 813.38,886.5 753.78,886.5 750.38,883.1 750.38,872.9 753.78,869.5 813.38,869.5 872.98,869.5 876.38,866.1 876.38,855.9 872.98,852.5 813.38,852.5 753.78,852.5 750.38,849.1 750.38,838.9 753.78,835.5 809.98,835.5 813.38,832.1 813.38,827 813.38,806 819,800.38 823.17,796.21 826.85,796.21 831.66,796.21 838.87,788.99 838.87,784.19 837.03,782.35 835.19,780.51 835.19,775.7 842.41,768.49 847.21,768.49 849.05,770.33 850.89,772.16 855.7,772.16 862.91,764.95 862.91,760.14 861.07,758.3 859.23,756.47 859.23,751.66 866.45,744.45 871.26,744.45 873.09,746.28 874.93,748.12 879.74,748.12 886.95,740.91 886.95,736.1 885.11,734.26 883.28,732.42 883.28,727.62 890.49,720.4 895.3,720.4 897.14,722.24 898.97,724.08 903.78,724.08 910.99,716.87 910.99,712.06 909.16,710.22 907.32,708.38 907.32,703.57 914.53,696.36 919.34,696.36 921.18,698.2 923.02,700.04 927.82,700.04 935.04,692.83 935.04,688.02 933.2,686.18 931.36,684.34 931.36,679.53 938.57,672.32 943.38,672.32 945.22,674.16 947.06,676 951.87,676 959.08,668.79 959.08,663.98 959.08,660.3 959.69,659.69 965.38,654 968.98,650.39 973.79,650.39 976.36,652.96 981.17,652.96 988.38,645.75 988.38,640.94 985.81,638.37 985.81,633.56 1000.69,618.69 1045,574.38 v1(1045,300) v1@1045,297 ; v1@2048.53,230.53 2060.5,230.53 2071.75,230.53 2075.5,226.78 2075.5,218.7 2079.25,214.95 2086.75,214.95 2090.5,218.7 2090.5,230.53 2090.5,242.36 2094.25,246.11 2101.75,246.11 2105.5,242.36 2105.5,230.53 2105.5,218.7 2109.25,214.95 2116.75,214.95 2120.5,218.7 2120.5,230.53 2120.5,242.36 2124.25,246.11 2131.75,246.11 2135.5,242.36 2135.5,230.53 2135.5,218.7 2139.25,214.95 2146.75,214.95 2150.5,218.7 2150.5,230.53 2150.5,242.36 2154.25,246.11 2161.75,246.11 2165.5,242.36 2165.5,230.53 2165.5,218.7 2169.25,214.95 2176.75,214.95 2180.5,218.7 2180.5,230.53 2180.5,242.36 2184.25,246.11 2191.75,246.11 2195.5,242.36 2195.5,230.53 2195.5,218.7 2199.25,214.95 2206.75,214.95 2210.5,218.7 2210.5,230.53 2210.5,242.36 2214.25,246.11 2221.75,246.11 2225.5,242.36 2225.5,230.53 2225.5,218.7 2229.25,214.95 2236.75,214.95 2240.5,218.7 2240.5,230.53 2240.5,242.36 2244.25,246.11 2251.75,246.11 2255.5,242.36 2255.5,230.53 2255.5,218.7 2259.25,214.95 2266.75,214.95 2270.5,218.7 2270.5,230.53 2270.5,242.36 2274.25,246.11 2281.75,246.11 2285.5,242.36 2285.5,230.53 2285.5,218.7 2289.25,214.95 2296.75,214.95 2300.5,218.7 2300.5,230.53 2300.5,242.36 2304.25,246.11 2311.75,246.11 2315.5,242.36 2315.5,230.53 2315.5,218.7 2319.25,214.95 2326.75,214.95 2330.5,218.7 2330.5,230.53 2330.5,242.36 2334.25,246.11 2341.75,246.11 2345.5,242.36 2345.5,230.53 2345.5,218.7 2349.25,214.95 2356.75,214.95 2360.5,218.7 2360.5,230.53 2360.5,242.36 2364.25,246.11 2371.75,246.11 2375.5,242.36 2375.5,230.53 2375.5,218.7 2379.25,214.95 2386.75,214.95 2390.5,218.7 2390.5,226.78 2394.25,230.53 2398,230.53 2462.47,230.53 2463,230 2488,255 2521,255 2526.5,260.5 2560.86,294.86 2565.66,294.86 2570.05,290.47 2574.86,290.47 2582.07,297.68 2582.07,302.49 2575.28,309.28 2568.49,316.07 2568.49,320.88 2575.71,328.09 2580.51,328.09 2587.3,321.3 2594.09,314.51 2598.9,314.51 2606.11,321.73 2606.11,326.53 2599.32,333.32 2592.53,340.11 2592.53,344.92 2599.75,352.13 2604.56,352.13 2611.34,345.34 2618.13,338.56 2622.94,338.56 2630.15,345.77 2630.15,350.58 2623.36,357.36 2616.58,364.15 2616.58,368.96 2623.79,376.17 2628.6,376.17 2635.39,369.39 2642.17,362.6 2646.98,362.6 2654.19,369.81 2654.19,374.62 2647.41,381.41 2640.62,388.19 2640.62,393 2647.83,400.22 2652.64,400.22 2659.43,393.43 2666.22,386.64 2671.02,386.64 2678.24,393.85 2678.24,398.66 2671.45,405.45 2664.66,412.24 2664.66,417.04 2671.87,424.26 2676.68,424.26 2683.47,417.47 2690.26,410.68 2695.07,410.68 2702.28,417.89 2702.28,422.7 2697.89,427.09 2697.89,431.89 2701.5,435.5 2719.5,453.5 2719.5,1052.5 2665,1107 2665,1181 2688,1204 2747,1204 v1(2757,1194)
  Bottom Layer w6: v1@1045,291 v1(1045,300) 1045,499 1062,516 1080,516 1083.75,516 1087.5,519.75 1087.5,524.22 1091.25,527.97 1098.75,527.97 1102.5,524.22 1102.5,516 1102.5,507.78 1106.25,504.03 1113.75,504.03 1117.5,507.78 1117.5,516 1117.5,524.22 1121.25,527.97 1128.75,527.97 1132.5,524.22 1132.5,516 1132.5,507.78 1136.25,504.03 1143.75,504.03 1147.5,507.78 1147.5,516 1147.5,524.22 1151.25,527.97 1158.75,527.97 1162.5,524.22 1162.5,516 1162.5,507.78 1166.25,504.03 1173.75,504.03 1177.5,507.78 1177.5,516 1177.5,524.22 1181.25,527.97 1188.75,527.97 1192.5,524.22 1192.5,516 1192.5,507.78 1196.25,504.03 1203.75,504.03 1207.5,507.78 1207.5,516 1207.5,524.22 1211.25,527.97 1218.75,527.97 1222.5,524.22 1222.5,516 1222.5,507.78 1226.25,504.03 1233.75,504.03 1237.5,507.78 1237.5,516 1237.5,524.22 1241.25,527.97 1248.75,527.97 1252.5,524.22 1252.5,516 1252.5,507.78 1256.25,504.03 1263.75,504.03 1267.5,507.78 1267.5,516 1267.5,524.22 1271.25,527.97 1278.75,527.97 1282.5,524.22 1282.5,516 1282.5,507.78 1286.25,504.03 1293.75,504.03 1297.5,507.78 1297.5,516 1297.5,524.22 1301.25,527.97 1308.75,527.97 1312.5,524.22 1312.5,516 1312.5,507.78 1316.25,504.03 1323.75,504.03 1327.5,507.78 1327.5,516 1327.5,524.22 1331.25,527.97 1338.75,527.97 1342.5,524.22 1342.5,516 1342.5,507.78 1346.25,504.03 1353.75,504.03 1357.5,507.78 1357.5,516 1357.5,524.22 1361.25,527.97 1368.75,527.97 1372.5,524.22 1372.5,516 1372.5,507.78 1376.25,504.03 1383.75,504.03 1387.5,507.78 1387.5,516 1387.5,524.22 1391.25,527.97 1398.75,527.97 1402.5,524.22 1402.5,516 1402.5,507.78 1406.25,504.03 1413.75,504.03 1417.5,507.78 1417.5,516 1417.5,524.22 1421.25,527.97 1428.75,527.97 1432.5,524.22 1432.5,516 1432.5,507.78 1436.25,504.03 1443.75,504.03 1447.5,507.78 1447.5,516 1447.5,524.22 1451.25,527.97 1458.75,527.97 1462.5,524.22 1462.5,516 1462.5,507.78 1466.25,504.03 1473.75,504.03 1477.5,507.78 1477.5,516 1477.5,524.22 1481.25,527.97 1488.75,527.97 1492.5,524.22 1492.5,516 1492.5,507.78 1496.25,504.03 1503.75,504.03 1507.5,507.78 1507.5,512.25 1511.25,516 1564,516 1713.5,516 1747.5,482 1747.5,405.5 1955,198 1977,198 2009.53,230.53 v1@2048.53,230.53 ; J1.3@2683.6,1236.74 2683.6,1202.4 2692,1194 v1(2757,1194)
EM_CLK: J1.46@2352.89,1329.26 U2.38 | length 2512.6
  Top Layer w6: v1@2068,1351 2081,1338 2127,1338 2186,1279 2186,1248 2195,1239 2195,928 2254.5,868.5 2254.5,847 2254.5,843.25 2258.25,839.5 2266.18,839.5 2269.93,835.75 2269.93,828.25 2266.18,824.5 2254.5,824.5 2242.82,824.5 2239.07,820.75 2239.07,813.25 2242.82,809.5 2254.5,809.5 2266.18,809.5 2269.93,805.75 2269.93,798.25 2266.18,794.5 2254.5,794.5 2242.82,794.5 2239.07,790.75 2239.07,783.25 2242.82,779.5 2254.5,779.5 2266.18,779.5 2269.93,775.75 2269.93,768.25 2266.18,764.5 2254.5,764.5 2242.82,764.5 2239.07,760.75 2239.07,753.25 2242.82,749.5 2254.5,749.5 2266.18,749.5 2269.93,745.75 2269.93,738.25 2266.18,734.5 2254.5,734.5 2242.82,734.5 2239.07,730.75 2239.07,723.25 2242.82,719.5 2254.5,719.5 2266.18,719.5 2269.93,715.75 2269.93,708.25 2266.18,704.5 2254.5,704.5 2242.82,704.5 2239.07,700.75 2239.07,693.25 2242.82,689.5 2254.5,689.5 2266.18,689.5 2269.93,685.75 2269.93,678.25 2266.18,674.5 2254.5,674.5 2242.82,674.5 2239.07,670.75 2239.07,663.25 2242.82,659.5 2254.5,659.5 2266.18,659.5 2269.93,655.75 2269.93,648.25 2266.18,644.5 2254.5,644.5 2242.82,644.5 2239.07,640.75 2239.07,633.25 2242.82,629.5 2254.5,629.5 2266.18,629.5 2269.93,625.75 2269.93,618.25 2266.18,614.5 2254.5,614.5 2242.82,614.5 2239.07,610.75 2239.07,603.25 2242.82,599.5 2254.5,599.5 2266.18,599.5 2269.93,595.75 2269.93,588.25 2266.18,584.5 2254.5,584.5 2242.82,584.5 2239.07,580.75 2239.07,573.25 2242.82,569.5 2254.5,569.5 2266.18,569.5 2269.93,565.75 2269.93,558.25 2266.18,554.5 2254.5,554.5 2242.82,554.5 2239.07,550.75 2239.07,543.25 2242.82,539.5 2254.5,539.5 2266.18,539.5 2269.93,535.75 2269.93,528.25 2266.18,524.5 2254.5,524.5 2242.82,524.5 2239.07,520.75 2239.07,513.25 2242.82,509.5 2254.5,509.5 2266.18,509.5 2269.93,505.75 2269.93,498.25 2266.18,494.5 2254.5,494.5 2242.82,494.5 2239.07,490.75 2239.07,483.25 2242.82,479.5 2254.5,479.5 2266.18,479.5 2269.93,475.75 2269.93,468.25 2266.18,464.5 2254.5,464.5 2242.82,464.5 2239.07,460.75 2239.07,453.25 2242.82,449.5 2254.5,449.5 2266.18,449.5 2269.93,445.75 2269.93,438.25 2266.18,434.5 2258.25,434.5 2254.5,430.75 2254.5,427 2254.5,409.5 2260,404 2262.65,401.35 2267.95,401.35 2271.14,404.53 2276.44,404.53 2281.74,399.23 2281.74,393.92 2278.56,390.74 2278.56,385.44 2285.5,378.5 2287.49,376.51 2291.24,376.51 2294.99,380.26 2294.99,384.76 2298.74,388.51 2306.24,388.51 2309.99,384.76 2309.99,376.51 2309.99,368.26 2313.74,364.51 2321.24,364.51 2324.99,368.26 2324.99,376.51 2324.99,384.76 2328.74,388.51 2336.24,388.51 2339.99,384.76 2339.99,376.51 2339.99,368.26 2343.74,364.51 2351.24,364.51 2354.99,368.26 2354.99,376.51 2354.99,384.76 2358.74,388.51 2366.24,388.51 2369.99,384.76 2369.99,376.51 2369.99,368.26 2373.74,364.51 2381.24,364.51 2384.99,368.26 2384.99,376.51 2384.99,384.76 2388.74,388.51 2396.24,388.51 2399.99,384.76 2399.99,380.26 2403.74,376.51 2407,376.51 v1(2414,369.51)
  Top Layer w15: v1(2414,369.51) 2421,376.51 U2.38@2458.36,376.51
  Bottom Layer w6: v1@2068,1351 2068,1367 2124,1423 2297,1423 2352.89,1367.11 J1.46@2352.89,1329.26
  other v1: 2068,1350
